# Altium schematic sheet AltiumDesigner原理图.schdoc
size 113 x 96 mm
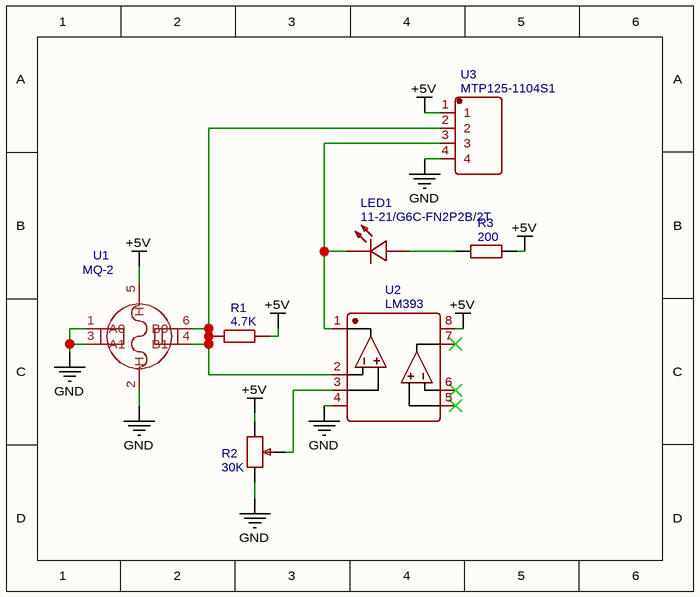
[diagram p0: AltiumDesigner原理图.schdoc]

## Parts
LED1  11-21/G6C-FN2P2B/2T  [LED1206-R-RD]
R1  4.7K  [R0805]
R2  30K  [RES-ADJ-TH_VZ067TL1B202]
R3  200  [R0805]
U1  MQ-2  [SENSOR-TH_MQ-2]
U2  LM393  [SOP-8_L4.9-W3.9-P1.27-LS6.0-BL]
U3  MTP125-1104S1  [HDR-TH_4P-P2.54-V]

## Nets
+5V: R1.2 R2.1 R3.2 U1.5(H) U2.8(VDD) U3.1
GND: R2.3 U1.1(A0) U1.2(H) U1.3(A1) U2.4(GND) U3.4
NetLED1_1: LED1.1(A) R3.1
NetLED1_2: LED1.2(K) U2.1 U3.3
NetR1_1: R1.1 U1.4(B1) U1.6(B0) U2.2 U3.2
NetR2_2: R2.2 U2.3

Not connected (* = marked no-connect by the designer): U2 5* 6* 7*

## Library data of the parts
LED1 = 11-21/G6C-FN2P2B/2T: BOM_Manufacturer: Everlight Elec; Contributor: LCSC
R1 = 4.7K: BOM_Manufacturer: Tyohm; BOM_Manufacturer Part: RMC08054.7K5%N; nameAlias: Resistance (Ohms); Contributor: LCSC
R2 = 30K: BOM_Manufacturer: HDK; BOM_Manufacturer Part: VZ067TL1B303; nameAlias: Resistance (Ohms); Contributor: LCSC
R3 = 200: BOM_Manufacturer: UniOhm; BOM_Manufacturer Part: 0805W8J0201T5E; nameAlias: Resistance (Ohms)
U1 = MQ-2: BOM_Manufacturer: Winsen
U2 = LM393: BOM_Manufacturer: PUOLOP; Contributor: LCSC
U3 = MTP125-1104S1: BOM_Manufacturer: MINTRON; Contributor: LCSC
